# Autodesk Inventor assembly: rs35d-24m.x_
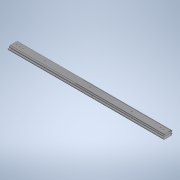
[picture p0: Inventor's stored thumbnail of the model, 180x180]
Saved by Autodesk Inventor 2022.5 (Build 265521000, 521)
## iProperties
Part Number: rs35d-24m.x_
Material: 一般
Document SubType Name: Assembly
Designer: ImaoCorp
Sending System: SOLIDWORKS 2017-2017317
MC: AMD64
MC_MODEL: Intel64 Family 6 Model 60 Stepping 3, GenuineIntel
OS: Windows_NT
FRU: Parasolid Version 29.0, build 201,  4-17-2017
FORMAT: text
GUISE: transmit
KEY: rs35d-24m
FILE: rs35d-24m.x_t
DATE: Tue Feb 05 16:29:32 2019
Author: ImaoCorp
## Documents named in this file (4)
- X:\14_SW2022-Inv2022\00_全2023-1023新製品(TCC)まで\r\rs35d-24m\RS35D-24M.iam
- X:\14_SW2022-Inv2022\00_全2023-1023新製品(TCC)まで\r\rs35d-24m\rs35d-24m_01.ipt
- X:\14_SW2022-Inv2022\00_全2023-1023新製品(TCC)まで\r\rs35d-24m\rs35d-24m_02.ipt
- X:\14_SW2022-Inv2022\00_全2023-1023新製品(TCC)まで\r\rs35d-24m\rs35d-24m_03.ipt
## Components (3 placed, 3 different names)
1. rs35d-24m_01
2. rs35d-24m_02
3. rs35d-24m_03
